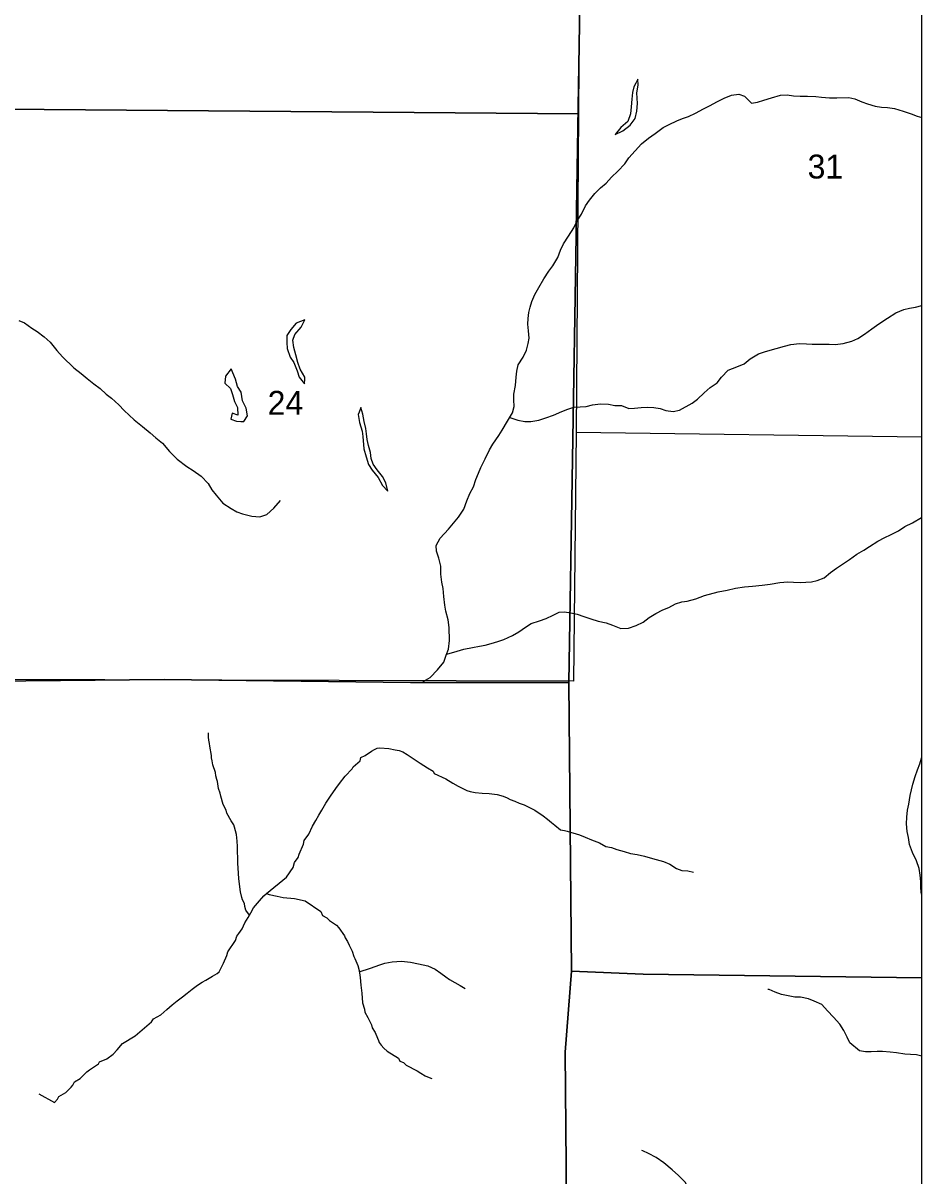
# Model space of a CAD drawing. Extents: x -10 to 158, y 8 to 33.
# Drawn here: x -4.565 to -2.991, y 18.808 to 20.825 of the extents above; entities that cross this region are included whole.
import ezdxf

# ---------------------------------------------------------------- set-up
doc = ezdxf.new("R2010")
doc.units = 0
for name, color, linetype in [('GM_X_Corporation', 7, 'Continuous'), ('GM_X_Minor_Lake', 7, 'Continuous'), ('GM_X_Minor_River', 7, 'Continuous'), ('GM_X_Section_Text', 7, 'Continuous')]:
    doc.layers.add(name, color=color, linetype=linetype)

msp = doc.modelspace()

# ---------------------------------------------------------------- linework, layer by layer
at = {"layer": 'GM_X_Corporation'}
for points in [[(-6.5893, 20.6717), (-6.0595, 20.6729), (-5.6577, 20.6646), (-5.6585, 20.2456), (-5.6615, 19.6886), (-5.4035, 19.6838), (-5.0683, 19.6778), (-4.7415, 19.6726), (-4.3178, 19.6768), (-3.8866, 19.6713), (-3.6094, 19.6717), (-3.6048, 19.1662), (-3.4794, 19.161), (-2.9914, 19.1544), (-2.9914, 22.8183), (-9.7914, 22.8183)], [(-6.5893, 20.6717), (-6.0595, 20.6729), (-5.6577, 20.6646), (-5.6585, 20.2456), (-5.6615, 19.6886), (-5.4035, 19.6838), (-5.0683, 19.6778), (-4.7415, 19.6726), (-4.3178, 19.6768), (-3.8866, 19.6713), (-3.6094, 19.6717), (-3.5966, 20.453), (-3.5964, 20.4615), (-3.5852, 21.1498), (-3.5851, 21.1507), (-3.5803, 22.8183), (-9.7914, 22.8183)], [(-2.9914, 16.0183), (-2.9914, 19.1544), (-3.4794, 19.161), (-3.6048, 19.1662), (-3.6094, 19.6717), (-3.8866, 19.6713), (-4.3178, 19.6768), (-4.7415, 19.6726), (-5.0683, 19.6778), (-5.4035, 19.6838), (-5.6615, 19.6886), (-5.6585, 20.2456), (-5.6577, 20.6646), (-6.0595, 20.6729), (-6.5893, 20.6717)], [(-3.613, 18.695), (-3.6159, 19.0246), (-3.6048, 19.1662), (-3.6094, 19.6717), (-3.8866, 19.6713), (-4.3178, 19.6768), (-4.7415, 19.6726), (-5.0683, 19.6778), (-5.4035, 19.6838), (-5.6615, 19.6886), (-5.6625, 19.6663), (-5.6789, 18.2975)]]:
    msp.add_lwpolyline(points, dxfattribs=at)
for points in [[(-2.9914, 19.1544), (-2.9914, 22.8183), (-3.5803, 22.8183), (-3.5851, 21.1507), (-3.5852, 21.1498), (-3.5964, 20.4615), (-3.5966, 20.453), (-3.6094, 19.6717), (-3.6048, 19.1662), (-3.4794, 19.161)], [(-3.5861, 21.6664), (-3.5893, 21.101), (-3.5927, 20.6663), (-4.5996, 20.6749), (-4.5923, 21.6703)], [(-2.9914, 20.1011), (-2.9914, 21.1049), (-3.5893, 21.101), (-3.5927, 20.6663), (-3.5967, 20.1095)], [(-3.5927, 20.6663), (-3.5967, 20.1095), (-3.6012, 19.6737), (-4.6276, 19.6769), (-4.5996, 20.6749)], [(-3.6338, 16.0183), (-2.9914, 16.0183), (-2.9914, 19.1544), (-3.4794, 19.161), (-3.6048, 19.1662), (-3.6159, 19.0246), (-3.613, 18.695), (-3.6057, 18.5118), (-3.6167, 17.6595), (-3.6311, 16.2195)]]:
    msp.add_lwpolyline(points, close=True, dxfattribs=at)
at = {"layer": 'GM_X_Minor_Lake'}
for points in [[(-3.5285, 20.6304), (-3.5149, 20.637), (-3.5022, 20.647), (-3.4932, 20.6585), (-3.4904, 20.6711), (-3.489, 20.6844), (-3.4895, 20.6939), (-3.4904, 20.7034), (-3.4883, 20.7167), (-3.4884, 20.7273), (-3.4922, 20.7205)], [(-3.4922, 20.7205), (-3.4959, 20.7139), (-3.498, 20.704), (-3.4994, 20.6922), (-3.5003, 20.6789), (-3.5017, 20.6668), (-3.5061, 20.6531), (-3.5184, 20.6426), (-3.5285, 20.6304)], [(-4.0714, 20.3063), (-4.0868, 20.3004), (-4.0962, 20.2889), (-4.1029, 20.2789), (-4.1031, 20.2667), (-4.1022, 20.2557), (-4.0971, 20.241), (-4.0905, 20.2312), (-4.085, 20.2169), (-4.0814, 20.2055), (-4.0718, 20.1942), (-4.0716, 20.2021)], [(-4.0716, 20.2021), (-4.0716, 20.206), (-4.0797, 20.2196), (-4.0837, 20.2317), (-4.0873, 20.2449), (-4.0908, 20.2574), (-4.0925, 20.2707), (-4.0892, 20.2802), (-4.078, 20.2933), (-4.0714, 20.3063)], [(-4.2004, 20.2203), (-4.2101, 20.2073), (-4.2114, 20.1951), (-4.2014, 20.1857), (-4.1979, 20.1755), (-4.1947, 20.1634), (-4.1892, 20.1525), (-4.1887, 20.1392), (-4.1986, 20.1429), (-4.2007, 20.1322), (-4.1908, 20.1285), (-4.1833, 20.1282)], [(-4.1833, 20.1282), (-4.1779, 20.1279), (-4.172, 20.1383), (-4.1741, 20.1515), (-4.1807, 20.1644), (-4.1831, 20.1795), (-4.1893, 20.1893), (-4.1929, 20.2025), (-4.2004, 20.2203)], [(-3.9765, 20.1443), (-3.9778, 20.1404), (-3.9757, 20.1264), (-3.9713, 20.1112), (-3.9697, 20.1018), (-3.9679, 20.0805), (-3.9643, 20.0665), (-3.9599, 20.0529), (-3.9537, 20.0431), (-3.9433, 20.0304), (-3.9355, 20.0164), (-3.9263, 20.0063)], [(-3.9263, 20.0063), (-3.9299, 20.0207), (-3.9354, 20.032), (-3.9446, 20.0436), (-3.9516, 20.0538), (-3.9551, 20.0636), (-3.9564, 20.0738), (-3.96, 20.0863), (-3.9624, 20.0966), (-3.9633, 20.1064), (-3.9649, 20.1159), (-3.9677, 20.128), (-3.9698, 20.1409), (-3.9737, 20.1526), (-3.9765, 20.1443)]]:
    msp.add_lwpolyline(points, dxfattribs=at)
at = {"layer": 'GM_X_Minor_River'}
for points in [[(-3.8645, 19.6733), (-3.8522, 19.6803), (-3.8395, 19.6934), (-3.8283, 19.7068), (-3.8239, 19.719), (-3.8198, 19.7297), (-3.8185, 19.7449), (-3.8188, 19.7677), (-3.8205, 19.7813), (-3.8245, 19.7965), (-3.8265, 19.8067), (-3.8279, 19.8222), (-3.8296, 19.8359), (-3.8316, 19.8473), (-3.8333, 19.8609), (-3.8335, 19.8753), (-3.8367, 19.889), (-3.8411, 19.9014), (-3.8416, 19.9113), (-3.8345, 19.9239), (-3.8199, 19.9397), (-3.811, 19.9501), (-3.8024, 19.9608), (-3.7931, 19.975), (-3.788, 19.9895), (-3.7824, 20.0021), (-3.7765, 20.0139), (-3.7721, 20.0265), (-3.7677, 20.0376), (-3.7633, 20.0479), (-3.7559, 20.0628), (-3.7485, 20.0784), (-3.7422, 20.0888), (-3.7318, 20.1037), (-3.7262, 20.1133), (-3.7166, 20.1286), (-3.708, 20.1431), (-3.7051, 20.1546), (-3.7057, 20.166), (-3.7054, 20.1758), (-3.7026, 20.1911), (-3.7013, 20.2055), (-3.7006, 20.2165), (-3.6981, 20.2272), (-3.6892, 20.241), (-3.6837, 20.2528), (-3.6804, 20.2646), (-3.679, 20.2741), (-3.6799, 20.2867), (-3.6809, 20.2988), (-3.6806, 20.3087), (-3.6796, 20.3189), (-3.6771, 20.3285), (-3.6742, 20.3384), (-3.6686, 20.3506), (-3.6616, 20.3625), (-3.6534, 20.3781), (-3.6441, 20.3912), (-3.6374, 20.4007), (-3.6289, 20.4149), (-3.6237, 20.4279), (-3.619, 20.4393), (-3.6097, 20.4524), (-3.6007, 20.4673), (-3.5948, 20.4791), (-3.5874, 20.491), (-3.5804, 20.5055), (-3.5733, 20.5155), (-3.5636, 20.5274), (-3.5539, 20.537), (-3.5441, 20.5455), (-3.5348, 20.5559), (-3.5239, 20.5662), (-3.5115, 20.5793), (-3.5041, 20.5893), (-3.4932, 20.6016), (-3.4824, 20.6142), (-3.47, 20.6239), (-3.4584, 20.6324), (-3.4441, 20.6425), (-3.4339, 20.6479), (-3.4203, 20.6545), (-3.4105, 20.6585), (-3.3999, 20.662), (-3.3875, 20.6675), (-3.3739, 20.6753), (-3.3634, 20.6803), (-3.3491, 20.6881), (-3.3374, 20.694), (-3.3245, 20.6991), (-3.312, 20.7008), (-3.3018, 20.6975), (-3.2898, 20.6855), (-3.2789, 20.6871), (-3.2679, 20.6903), (-3.2547, 20.6947), (-3.2392, 20.699), (-3.227, 20.6996), (-3.216, 20.6978), (-3.2046, 20.6976), (-3.1917, 20.6974)], [(-3.1917, 20.6974), (-3.1773, 20.6968), (-3.1674, 20.6958), (-3.1534, 20.6945), (-3.1401, 20.6946), (-3.1196, 20.6949), (-3.1086, 20.6931), (-3.0968, 20.6876), (-3.0865, 20.6843), (-3.0735, 20.6799), (-3.0621, 20.6782), (-3.0518, 20.6775), (-3.0397, 20.6758), (-3.0241, 20.6714), (-3.01, 20.6663), (-2.9997, 20.6627), (-2.9914, 20.6599)], [(-3.7126, 20.1353), (-3.6988, 20.1304), (-3.6862, 20.1282), (-3.676, 20.128), (-3.6616, 20.1305), (-3.6499, 20.1348), (-3.6363, 20.1395), (-3.6219, 20.1454), (-3.611, 20.1497), (-3.6004, 20.1533), (-3.5898, 20.1538), (-3.5792, 20.1547), (-3.5678, 20.1571), (-3.5542, 20.1592), (-3.5398, 20.1586), (-3.5287, 20.1561), (-3.5174, 20.1559), (-3.5044, 20.1511), (-3.4945, 20.1516), (-3.4828, 20.1525), (-3.471, 20.153), (-3.4608, 20.1524), (-3.4498, 20.1507), (-3.4395, 20.1474), (-3.4269, 20.1456), (-3.4156, 20.1481), (-3.3937, 20.1605), (-3.384, 20.1675), (-3.3723, 20.1786), (-3.3618, 20.1875), (-3.3498, 20.1956), (-3.3423, 20.2056), (-3.3307, 20.2179), (-3.3156, 20.2238), (-3.3024, 20.2293), (-3.2919, 20.2378), (-3.2772, 20.2467), (-3.2667, 20.2502), (-3.2568, 20.253), (-3.2463, 20.2562), (-3.2319, 20.2602), (-3.2209, 20.263), (-3.2054, 20.2647), (-3.1932, 20.2641), (-3.1834, 20.2635), (-3.164, 20.2633), (-3.1538, 20.2635), (-3.1435, 20.2632), (-3.1291, 20.2646), (-3.114, 20.2689), (-3.1035, 20.2736), (-3.0922, 20.281), (-3.079, 20.2906), (-3.0666, 20.2992), (-3.0516, 20.3092), (-3.0373, 20.3181), (-3.0229, 20.3244), (-3.0131, 20.3264), (-3.0025, 20.3281), (-2.9914, 20.331)], [(-4.5718, 20.3047), (-4.5622, 20.3007), (-4.5492, 20.2913), (-4.5397, 20.2854), (-4.5274, 20.2764), (-4.5174, 20.2671), (-4.5055, 20.2524), (-4.4955, 20.2415), (-4.4755, 20.222), (-4.4628, 20.212), (-4.4521, 20.2034), (-4.4406, 20.194), (-4.4298, 20.1858), (-4.4191, 20.1761), (-4.4095, 20.169), (-4.3968, 20.1574), (-4.3876, 20.1476), (-4.3703, 20.1311), (-4.3554, 20.1196), (-4.3419, 20.1083), (-4.3323, 20.0997), (-4.3205, 20.09), (-4.3081, 20.0757), (-4.295, 20.0622), (-4.2782, 20.0492), (-4.2671, 20.0425), (-4.2529, 20.0328), (-4.2406, 20.0197), (-4.234, 20.0087), (-4.2267, 19.999), (-4.2147, 19.9854), (-4.2006, 19.9761), (-4.1903, 19.9702), (-4.1803, 19.9665), (-4.1644, 19.9626), (-4.1503, 19.9612), (-4.1382, 19.9652), (-4.1255, 19.9767), (-4.1139, 19.9902)], [(-3.8231, 19.721), (-3.8046, 19.7261), (-3.7929, 19.7297), (-3.7781, 19.7329), (-3.7657, 19.7353), (-3.7558, 19.737), (-3.7452, 19.7398), (-3.7335, 19.743), (-3.7233, 19.7469), (-3.7082, 19.7539), (-3.6969, 19.7602), (-3.6853, 19.7683), (-3.6751, 19.7745), (-3.6608, 19.7792), (-3.649, 19.7832), (-3.6366, 19.789), (-3.6264, 19.7945), (-3.617, 19.7954), (-3.6056, 19.7936), (-3.5949, 19.7911), (-3.5831, 19.7867), (-3.5709, 19.7827), (-3.5583, 19.779), (-3.5439, 19.7758), (-3.5332, 19.7718), (-3.5183, 19.7659), (-3.505, 19.7664), (-3.4914, 19.7712), (-3.4794, 19.777), (-3.4689, 19.7851), (-3.4572, 19.7921), (-3.4451, 19.7984), (-3.4346, 19.8027), (-3.4229, 19.8089), (-3.4115, 19.8128), (-3.4021, 19.8137), (-3.3873, 19.8181), (-3.3722, 19.8236), (-3.348, 19.83), (-3.3321, 19.8332), (-3.3178, 19.8365), (-3.3022, 19.8389), (-3.2882, 19.8403), (-3.2712, 19.8416), (-3.2568, 19.8433), (-3.2401, 19.8462), (-3.2261, 19.8475), (-3.2159, 19.8473), (-3.2048, 19.8467), (-3.1847, 19.8477), (-3.1745, 19.8497), (-3.1628, 19.8544), (-3.1512, 19.8641), (-3.141, 19.8714), (-3.1286, 19.8795), (-3.1181, 19.8869), (-3.1053, 19.8958), (-3.0933, 19.9032), (-3.0831, 19.9097), (-3.0688, 19.9187), (-3.0564, 19.9253), (-3.0462, 19.9296), (-3.0323, 19.9366), (-3.0214, 19.9443), (-3.0078, 19.951), (-2.992, 19.9603), (-2.9914, 19.9605)], [(-4.1685, 19.2641), (-4.1746, 19.2729), (-4.1763, 19.2797), (-4.1771, 19.2846), (-4.1806, 19.291), (-4.1815, 19.2955), (-4.1843, 19.3053), (-4.187, 19.3276), (-4.1875, 19.3378), (-4.1886, 19.3553), (-4.1895, 19.3844), (-4.19, 19.3939), (-4.1913, 19.4056), (-4.1946, 19.4181), (-4.1954, 19.4222), (-4.2001, 19.4293), (-4.2079, 19.4428), (-4.2091, 19.4481), (-4.2146, 19.4582), (-4.2186, 19.4726), (-4.2195, 19.4779), (-4.2223, 19.4858), (-4.2244, 19.4982), (-4.2252, 19.502), (-4.2272, 19.5084), (-4.2277, 19.5141), (-4.2325, 19.5273), (-4.2337, 19.5341), (-4.2346, 19.5397), (-4.235, 19.5439), (-4.2376, 19.5598), (-4.238, 19.5647), (-4.2393, 19.5707), (-4.2398, 19.576), (-4.2398, 19.5798), (-4.2403, 19.5836)], [(-4.1375, 19.3018), (-4.1384, 19.302), (-4.1037, 19.3306), (-4.0919, 19.3475), (-4.0897, 19.3563), (-4.0831, 19.3655), (-4.0813, 19.3712), (-4.0736, 19.3884), (-4.0726, 19.3949), (-4.0645, 19.406), (-4.0579, 19.4198), (-4.0524, 19.4297), (-4.0472, 19.4393), (-4.0417, 19.4481), (-4.0344, 19.4604), (-4.0266, 19.4726), (-4.0174, 19.4861), (-4.0107, 19.4949), (-4.0011, 19.5076), (-3.9888, 19.5203), (-3.987, 19.5238), (-3.9747, 19.5346), (-3.9733, 19.5403), (-3.9661, 19.5438), (-3.9545, 19.5513), (-3.9496, 19.554), (-3.9451, 19.5564), (-3.9402, 19.5572), (-3.9247, 19.556), (-3.9136, 19.5539), (-3.9064, 19.5525), (-3.8999, 19.5503), (-3.8923, 19.5456), (-3.8873, 19.5419), (-3.8697, 19.5304), (-3.8567, 19.5223), (-3.8471, 19.5164), (-3.8448, 19.5123), (-3.8249, 19.5028), (-3.8126, 19.4951), (-3.8031, 19.4903), (-3.7958, 19.4867), (-3.7878, 19.4826), (-3.7821, 19.4805), (-3.7733, 19.4787), (-3.7608, 19.4778), (-3.7487, 19.4773), (-3.735, 19.4756), (-3.7244, 19.4728), (-3.7171, 19.4695), (-3.7118, 19.467), (-3.7041, 19.4637), (-3.6961, 19.4604), (-3.6877, 19.4572), (-3.6782, 19.4528), (-3.6687, 19.448), (-3.6545, 19.4381), (-3.6468, 19.4321), (-3.6399, 19.4266), (-3.6341, 19.4218), (-3.6237, 19.4136), (-3.6168, 19.4123), (-3.6123, 19.4113)], [(-2.9914, 19.2997), (-2.9925, 19.3041), (-2.9933, 19.314), (-2.9931, 19.3235), (-2.9944, 19.3341), (-2.996, 19.3458), (-3.0008, 19.3595), (-3.0082, 19.3738), (-3.0133, 19.3878), (-3.015, 19.4003), (-3.017, 19.4109), (-3.0183, 19.4242), (-3.0181, 19.4356), (-3.0164, 19.4481), (-3.0146, 19.4588), (-3.0118, 19.474), (-3.0096, 19.4835), (-3.0071, 19.4934), (-3.0035, 19.5071), (-2.9994, 19.5186), (-2.995, 19.5293), (-2.9921, 19.5388), (-2.9914, 19.5414)], [(-3.6123, 19.4113), (-3.591, 19.4046), (-3.581, 19.4009), (-3.57, 19.3961), (-3.5559, 19.3906), (-3.5444, 19.3847), (-3.5349, 19.3825), (-3.5254, 19.3792), (-3.5128, 19.3756), (-3.5014, 19.3723), (-3.4896, 19.3702), (-3.477, 19.3673), (-3.4668, 19.3648), (-3.4568, 19.3619), (-3.4439, 19.3583), (-3.4328, 19.3535), (-3.421, 19.346), (-3.4114, 19.3424), (-3.4012, 19.3417), (-3.3913, 19.3396)], [(-4.5369, 18.9518), (-4.5097, 18.9363), (-4.5041, 18.9421), (-4.5019, 18.9467), (-4.4899, 18.9541), (-4.4806, 18.9634), (-4.4773, 18.9669), (-4.4743, 18.9726), (-4.4646, 18.9785), (-4.453, 18.9904), (-4.4482, 18.9939), (-4.4328, 19.0044), (-4.4306, 19.0079), (-4.4178, 19.0127), (-4.4066, 19.0208), (-4.3996, 19.0289), (-4.3906, 19.0397), (-4.3682, 19.053), (-4.3398, 19.0778), (-4.3365, 19.0831), (-4.3233, 19.0898), (-4.3129, 19.0991), (-4.3036, 19.1072), (-4.295, 19.1142), (-4.2856, 19.1216), (-4.2774, 19.1281), (-4.2688, 19.1347), (-4.2617, 19.1398), (-4.2557, 19.1441), (-4.2509, 19.1468), (-4.2445, 19.1507), (-4.2332, 19.1574), (-4.2246, 19.1621), (-4.2213, 19.1652), (-4.2187, 19.1709), (-4.2139, 19.1801), (-4.2077, 19.1935), (-4.2063, 19.2003), (-4.193, 19.2199), (-4.1905, 19.2275), (-4.1868, 19.2325), (-4.1809, 19.2406), (-4.1762, 19.2509), (-4.1706, 19.2605), (-4.1659, 19.2685), (-4.1611, 19.2769), (-4.1507, 19.2896), (-4.1429, 19.2981), (-4.1384, 19.302), (-4.1338, 19.3005), (-4.1198, 19.2974), (-4.1095, 19.2953), (-4.0898, 19.2934), (-4.0708, 19.2895), (-4.0432, 19.2707), (-4.0404, 19.2639), (-4.0328, 19.2595), (-4.0281, 19.2551), (-4.0159, 19.247), (-4.012, 19.2421), (-4.0019, 19.2283), (-4.0011, 19.2245), (-3.9968, 19.2181), (-3.9937, 19.2117), (-3.9913, 19.2072), (-3.9886, 19.2016), (-3.9858, 19.1922), (-3.9842, 19.1884), (-3.9787, 19.1764), (-3.9766, 19.1673), (-3.9758, 19.1636), (-3.9745, 19.1552), (-3.9732, 19.142), (-3.9718, 19.1276), (-3.9703, 19.111), (-3.9671, 19.0997), (-3.9663, 19.0944), (-3.9612, 19.0854), (-3.9545, 19.0726), (-3.9533, 19.0673), (-3.9482, 19.0587), (-3.9443, 19.0493), (-3.9423, 19.0448), (-3.9411, 19.0414), (-3.9376, 19.0369), (-3.9334, 19.0317), (-3.9276, 19.0265), (-3.9073, 19.014), (-3.9053, 19.0091), (-3.8985, 19.0062), (-3.8938, 19.0021), (-3.8751, 18.9918), (-3.8682, 18.9881), (-3.8609, 18.983), (-3.8567, 18.9815), (-3.8491, 18.9782)], [(-3.9762, 19.1653), (-3.9566, 19.1715), (-3.9404, 19.1775), (-3.9314, 19.1806), (-3.9186, 19.1828), (-3.9023, 19.1838), (-3.8867, 19.1822), (-3.8723, 19.1794), (-3.8559, 19.1756), (-3.8433, 19.1697), (-3.8334, 19.1627), (-3.8246, 19.1564), (-3.818, 19.1516), (-3.7993, 19.141), (-3.7909, 19.1362)], [(-3.0213, 19.021), (-3.036, 19.0232), (-3.047, 19.0244), (-3.0603, 19.0257), (-3.0698, 19.0258), (-3.0801, 19.0251), (-3.09, 19.0251), (-3.1005, 19.0271), (-3.1174, 19.0411), (-3.1223, 19.0508), (-3.1279, 19.0625), (-3.1351, 19.0735), (-3.146, 19.0861), (-3.1565, 19.0968), (-3.1667, 19.1079), (-3.1802, 19.1138), (-3.1899, 19.1177), (-3.2042, 19.1206), (-3.2138, 19.1206), (-3.2258, 19.1234), (-3.2371, 19.1254), (-3.2484, 19.1293), (-3.2585, 19.1343), (-3.2611, 19.1341)], [(-2.9914, 19.0177), (-3.0011, 19.0198), (-3.0114, 19.0206), (-3.0213, 19.021)], [(-3.2799, 18.6205), (-3.2874, 18.6315), (-3.2953, 18.6417), (-3.3064, 18.6498), (-3.3175, 18.6579), (-3.3289, 18.6671), (-3.339, 18.6801), (-3.3495, 18.6931), (-3.3632, 18.7017), (-3.3772, 18.7122), (-3.3869, 18.7267), (-3.3924, 18.7399), (-3.3931, 18.7494), (-3.3926, 18.762), (-3.3937, 18.7719), (-3.3985, 18.785), (-3.4059, 18.7971), (-3.4173, 18.8087), (-3.4286, 18.8187), (-3.443, 18.8307), (-3.4566, 18.84), (-3.4697, 18.8471), (-3.4797, 18.8517), (-3.4816, 18.8525)]]:
    msp.add_lwpolyline(points, dxfattribs=at)

# ---------------------------------------------------------------- texts
at = {"layer": 'GM_X_Section_Text'}
for s, p in [('31', (-3.1915, 20.5534)), ('24', (-4.1365, 20.1399))]:
    msp.add_text(s, height=0.04186, rotation=0, dxfattribs=at).set_placement(p)

doc.saveas('drawing.dxf')
